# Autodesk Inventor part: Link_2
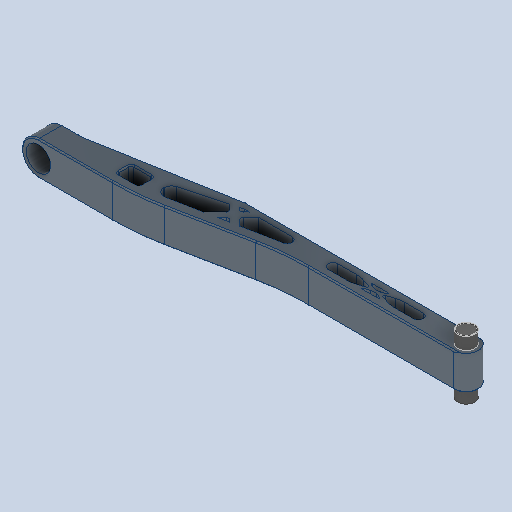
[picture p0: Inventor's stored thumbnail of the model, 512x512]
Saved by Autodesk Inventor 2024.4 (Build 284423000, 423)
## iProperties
Created: 2025-07
Part Number: Link_2
Material: Generic
Document SubType Name: Modeling
Designer: AdminForWorker
Density: 1 g/cm^3
Appearance: Default
Title: Link_2 v2
Author: AdminForWorker
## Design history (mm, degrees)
feature "Body1"
feature "Body2"
feature "Body3"
feature "Body4"
feature "Body5"
body "Solid1"
body "Solid2"
body "Solid3"
body "Solid4"
body "Solid5"
